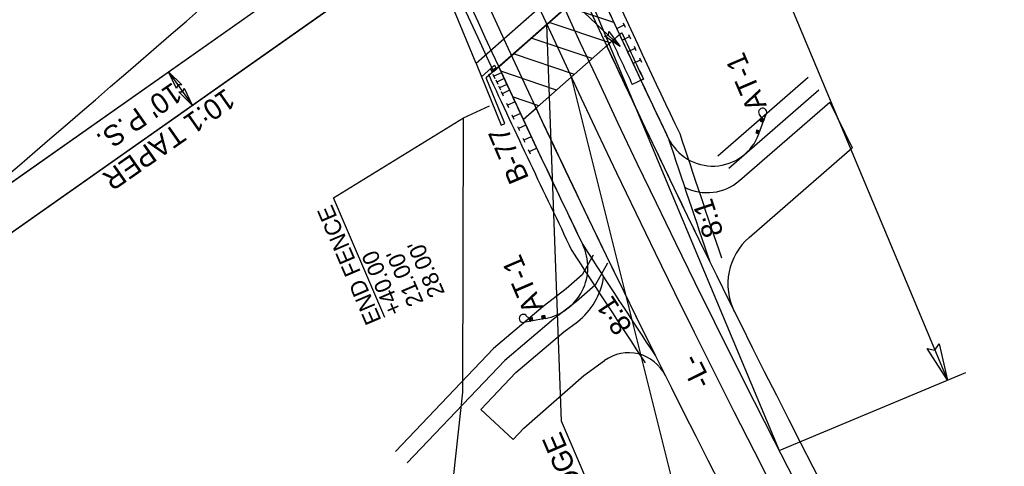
# Model space of a CAD drawing. Extents: x 1550950 to 1552827, y 809595 to 812050.
# Drawn here: x 1551746.5 to 1551986.2, y 810516.8 to 810625.6 of the extents above; entities that cross this region are included whole.
import ezdxf

# ---------------------------------------------------------------- set-up
doc = ezdxf.new("R2010")
doc.units = 0
for name, color, linetype in [('_CIVIL_CONSTRUCTION', 7, 'Continuous'), ('Construction Elements LEVEL', 7, 'Continuous'), ('Draft_Plan_Labels', 7, 'Continuous'), ('Drop Inlet Box Traffic Bearing 840 35-Bottom CELL', 7, 'Continuous'), ('Drop Inlet Box Type B 36 Dia-Bottom CELL', 7, 'Continuous'), ('Drop Inlet Grate 2 Narrow Slot and Flat Grates 840 29 36 Dia BD Apron-Top CELL', 7, 'Continuous'), ('Drop Inlet Grate 2 Narrow Slot and Flat Grates 840 29 36 Dia BD CELL', 7, 'Continuous'), ('Drop Inlet Grate 2 Narrow Slot and Flat Grates 840 29 36 Dia TB-Top CELL', 7, 'Continuous'), ('Drop Inlet Grate 2 Wide Slot and Flat Grates 840 20 36 Dia BD-Top CELL', 7, 'Continuous'), ('Drop Inlet Grate 3 Narrow Slot and Flat Grates 840 29 48 Dia-Top CELL', 7, 'Continuous'), ('E_NCDOT_Vertical_Profile_Ground_Line', 7, 'Continuous'), ('Junction Box with Slab Lid 840 31 66 Dia TB CELL', 7, 'Continuous'), ('P_HYD_Ditch_Flow_Arrow', 7, 'Continuous'), ('P_NCDOT_SS_Cut_Line', 7, 'Continuous'), ('P_NCDOT_SS_Transition_Line', 7, 'Continuous'), ('RipRap Pad at Outlet CELL', 7, 'Continuous'), ('Typical Terminator CELL', 7, 'Continuous'), ('V Ditch Special Lateral Detail CELL', 7, 'Continuous'), ('V Ditch Special Lateral with PSRM Detail CELL', 7, 'Continuous')]:
    doc.layers.add(name, color=color, linetype=linetype)

msp = doc.modelspace()

# ---------------------------------------------------------------- linework, layer by layer
at = {"layer": '_CIVIL_CONSTRUCTION'}
msp.add_line((1551782.78, 810612.91), (1551788.54, 810604.74), dxfattribs=at)
at = {"layer": 'Construction Elements LEVEL'}
for centre, radius, start, end in [((1554524.17, 811845.14), 2902, 205.10191, 205.4792), ((1551915.25, 810601.91), 12, 205.4792, 339.7079), ((1554524.17, 811845.14), 2932, 205.27393, 205.76247), ((1551872.17, 810565.26), 12.69, 280.4328, 25.7625)]:
    msp.add_arc(centre, radius, start, end, dxfattribs=at)
at = {"layer": 'Draft_Plan_Labels'}
for points in [[(1551871.67, 810641.73), (1551873.63, 810637.13), (1551892.72, 810619.04)], [(1551898.07, 810481.9), (1551878.45, 810527.75), (1551874.88, 810624.42)], [(1551941.7, 810409.34), (1551916.99, 810467.06), (1551880.83, 810611.6)], [(1551835.45, 810553.04), (1551822.97, 810582.2), (1551854.57, 810601.66)], [(1551862.89, 810445.08), (1551848.32, 810479.12), (1551854.4, 810534.8)]]:
    msp.add_lwpolyline(points, dxfattribs=at)
at = {"layer": 'Drop Inlet Box Traffic Bearing 840 35-Bottom CELL'}
for p, q in [((1551857.64, 810614.87), (1551844.4, 810647.29)), ((1551888.44, 810642.05), (1551857.64, 810614.87)), ((1551889.52, 810637.33), (1551860.13, 810611.4)), ((1551857.64, 810614.87), (1551863.75, 810599.91)), ((1551862.12, 810614.49), (1551858.94, 810611.68)), ((1551862.12, 810614.49), (1551862.56, 810613.54)), ((1551864.67, 810600.29), (1551860.13, 810611.4)), ((1551863.75, 810599.91), (1551864.67, 810600.29))]:
    msp.add_line(p, q, dxfattribs=at)
at = {"layer": 'Drop Inlet Box Type B 36 Dia-Bottom CELL'}
msp.add_line((1551738.42, 810569.43), (1551825.44, 810630.73), dxfattribs=at)
for centre, radius, start, end in [((1554524.17, 811845.14), 2902, 204.93866, 205.10191), ((1554524.17, 811845.14), 2902, 205.17218, 205.4792), ((1554524.17, 811845.14), 2932, 205.10292, 205.76247), ((1554653.7, 811503.31), 2894.89, 198.24966, 198.87905), ((1554332.71, 812152.3), 2915.37, 212.8525, 213.48904)]:
    msp.add_arc(centre, radius, start, end, dxfattribs=at)
at = {"layer": 'Drop Inlet Grate 2 Narrow Slot and Flat Grates 840 29 36 Dia BD Apron-Top CELL'}
for p, q in [((1551916.53, 810592.42), (1551938.49, 810611.53)), ((1551919.16, 810589.41), (1551941.12, 810608.51))]:
    msp.add_line(p, q, dxfattribs=at)
for points in [[(1551886.12, 810568.23), (1551883.43, 810563.41), (1551879.57, 810559.98), (1551874.01, 810555.72), (1551861.85, 810545.43), (1551838, 810520.39)], [(1551889.61, 810566.28), (1551886.59, 810560.88), (1551882.12, 810556.89), (1551876.52, 810552.61), (1551864.6, 810542.51), (1551840.9, 810517.63)]]:
    msp.add_lwpolyline(points, dxfattribs=at)
at = {"layer": 'Drop Inlet Grate 2 Narrow Slot and Flat Grates 840 29 36 Dia BD CELL'}
for p, q in [((1551800.94, 810947.98), (1551972.39, 810537.74)), ((1551759.95, 810930.85), (1551931.4, 810520.61)), ((1551931.4, 810520.61), (1551976.89, 810539.62))]:
    msp.add_line(p, q, dxfattribs=at)
msp.add_lwpolyline([(1551970.35, 810546.64), (1551972.39, 810537.74), (1551967.42, 810545.47), (1551969.34, 810545.03)], close=True, dxfattribs=at)
msp.add_arc((1554524.17, 811845.14), 2911.5, 194.24112, 221.47505, dxfattribs=at)
at = {"layer": 'Drop Inlet Grate 2 Narrow Slot and Flat Grates 840 29 36 Dia TB-Top CELL'}
for points in [[(1551889.99, 810622.69), (1551892.72, 810619.04), (1551888.88, 810621.57), (1551889.85, 810621.75)], [(1551784.74, 810608.79), (1551782.78, 810612.91), (1551786.04, 810609.67), (1551785.06, 810609.68)], [(1551786.58, 810608.86), (1551788.54, 810604.74), (1551785.28, 810607.98), (1551786.27, 810607.97)]]:
    msp.add_lwpolyline(points, close=True, dxfattribs=at)
at = {"layer": 'Drop Inlet Grate 2 Wide Slot and Flat Grates 840 20 36 Dia BD-Top CELL'}
msp.add_lwpolyline([(1551854.4, 810534.8), (1551854.57, 810601.66), (1551860.91, 810604.62)], dxfattribs=at)
at = {"layer": 'Drop Inlet Grate 3 Narrow Slot and Flat Grates 840 29 48 Dia-Top CELL'}
for p, q in [((1551889.43, 810619.19), (1551893.08, 810622.41)), ((1551898.37, 810611.09), (1551897.76, 810610.81)), ((1551869.11, 810601.25), (1551872.23, 810604.01))]:
    msp.add_line(p, q, dxfattribs=at)
msp.add_lwpolyline([(1551825.44, 810630.73), (1551738.42, 810569.43), (1551734.76, 810566.32), (1551727.95, 810574.29), (1551827.17, 810644.18)], dxfattribs=at)
for centre, radius, start, end in [((1554626.98, 811893.19), 3014.81, 204.93012, 205.16753), ((1554545.5, 811855.33), 2929.64, 204.95737, 206.09699), ((1554524.17, 811845.14), 2902, 205.17218, 205.4792), ((1554542.8, 811854.12), 2948.68, 205.08459, 206.38638), ((1554561.55, 811862.92), 2973.39, 205.10751, 205.75788), ((1554653.7, 811503.31), 2894.89, 198.24966, 198.87905), ((1554332.71, 812152.3), 2915.37, 212.8525, 213.48904)]:
    msp.add_arc(centre, radius, start, end, dxfattribs=at)
at = {"layer": 'E_NCDOT_Vertical_Profile_Ground_Line'}
for p, q in [((1551926.57, 810602.49), (1551927.22, 810601.48)), ((1551927.73, 810601.07), (1551928.33, 810602.69)), ((1551926.5, 810597.75), (1551927.73, 810601.07)), ((1551927.04, 810601.54), (1551926.8, 810600.88)), ((1551927.8, 810601.26), (1551926.8, 810600.88)), ((1551926.8, 810600.88), (1551927.56, 810600.6)), ((1551927.8, 810601.26), (1551927.04, 810601.54)), ((1551927.56, 810600.6), (1551927.04, 810601.54)), ((1551927.8, 810601.26), (1551927.47, 810601.38)), ((1551927.8, 810601.26), (1551927.47, 810601.38)), ((1551927.56, 810600.6), (1551927.8, 810601.26)), ((1551927.76, 810601.14), (1551927.71, 810601.01)), ((1551927.76, 810601.14), (1551927.71, 810601.01)), ((1551925.99, 810598.69), (1551925.75, 810598.03)), ((1551926.75, 810598.41), (1551925.75, 810598.03)), ((1551925.75, 810598.03), (1551926.5, 810597.75)), ((1551926.75, 810598.41), (1551925.99, 810598.69)), ((1551926.5, 810597.75), (1551925.99, 810598.69)), ((1551926.5, 810597.75), (1551926.75, 810598.41)), ((1551870.98, 810552.13), (1551869.3, 810551.82)), ((1551869.79, 810553.53), (1551870.6, 810552.78)), ((1551870.58, 810552.88), (1551871.27, 810553.01)), ((1551870.72, 810552.09), (1551870.58, 810552.88)), ((1551871.41, 810552.21), (1551870.58, 810552.88)), ((1551870.72, 810552.09), (1551870.66, 810552.43)), ((1551870.72, 810552.09), (1551870.66, 810552.43)), ((1551870.72, 810552.09), (1551871.27, 810553.01)), ((1551871.41, 810552.21), (1551870.72, 810552.09)), ((1551870.85, 810552.11), (1551870.98, 810552.13)), ((1551870.85, 810552.11), (1551870.98, 810552.13)), ((1551874.47, 810552.78), (1551870.98, 810552.13)), ((1551871.27, 810553.01), (1551871.41, 810552.21)), ((1551873.64, 810553.44), (1551874.32, 810553.57)), ((1551873.78, 810552.65), (1551873.64, 810553.44)), ((1551874.47, 810552.78), (1551873.64, 810553.44)), ((1551873.78, 810552.65), (1551874.32, 810553.57)), ((1551874.47, 810552.78), (1551873.78, 810552.65)), ((1551874.32, 810553.57), (1551874.47, 810552.78))]:
    msp.add_line(p, q, dxfattribs=at)
for centre, major_axis, start_param, end_param in [((1551927.4, 810603.03), (-0.931, 0.344), 3.141593, 7.214552), ((1551869.12, 810552.8), (0.18, -0.977), 2.210226, 6.283185)]:
    msp.add_ellipse(centre, major_axis=major_axis, ratio=0.995379, start_param=start_param, end_param=end_param, dxfattribs=at)
at = {"layer": 'Junction Box with Slab Lid 840 31 66 Dia TB CELL'}
for centre, radius, start, end in [((1554524.17, 811845.14), 2899, 204.64059, 205.48294), ((1554524.17, 811845.14), 2935, 204.83638, 205.7661), ((1554653.7, 811503.31), 2891.89, 198.2459, 198.87905), ((1554332.71, 812152.3), 2918.37, 212.84885, 213.48904)]:
    msp.add_arc(centre, radius, start, end, dxfattribs=at)
at = {"layer": 'P_HYD_Ditch_Flow_Arrow'}
msp.add_arc((1554524.17, 811845.14), 2917, 194.24112, 221.47505, dxfattribs=at)
at = {"layer": 'P_NCDOT_SS_Cut_Line'}
for p, q in [((1551891.21, 810624.85), (1551879.74, 810628.7)), ((1551890.24, 810619.9), (1551875.41, 810624.88)), ((1551885.91, 810616.08), (1551871.08, 810621.06)), ((1551881.58, 810612.26), (1551866.75, 810617.23)), ((1551877.25, 810608.44), (1551863.63, 810613)), ((1551872.92, 810604.62), (1551866.54, 810606.76))]:
    msp.add_line(p, q, dxfattribs=at)
at = {"layer": 'P_NCDOT_SS_Transition_Line'}
for p, q in [((1551886.63, 810634.78), (1551896.25, 810614.03)), ((1551891.89, 810623.44), (1551893.7, 810624.28)), ((1551893.46, 810624.8), (1551893.94, 810623.76)), ((1551893.2, 810620.61), (1551895.02, 810621.45)), ((1551894.78, 810621.97), (1551895.26, 810620.93)), ((1551896.09, 810619.13), (1551896.57, 810618.09)), ((1551894.52, 810617.77), (1551896.33, 810618.61)), ((1551863.15, 810614.06), (1551861.33, 810613.21)), ((1551863.15, 810614.06), (1551872.83, 810593.33)), ((1551895.83, 810614.94), (1551897.65, 810615.78)), ((1551897.4, 810616.3), (1551897.89, 810615.26)), ((1551861.09, 810613.73), (1551861.58, 810612.69)), ((1551861.75, 810612.31), (1551862.24, 810611.28)), ((1551863.81, 810612.64), (1551862, 810611.8)), ((1551862.41, 810610.9), (1551862.9, 810609.86)), ((1551864.47, 810611.23), (1551862.66, 810610.38)), ((1551863.08, 810609.48), (1551863.56, 810608.45)), ((1551865.13, 810609.81), (1551863.32, 810608.96)), ((1551863.74, 810608.07), (1551864.22, 810607.03)), ((1551865.79, 810608.4), (1551863.98, 810607.55)), ((1551865.06, 810605.24), (1551865.55, 810604.2)), ((1551867.12, 810605.57), (1551865.3, 810604.72)), ((1551866.38, 810602.41), (1551866.87, 810601.37)), ((1551868.44, 810602.73), (1551866.63, 810601.89)), ((1551867.71, 810599.58), (1551868.19, 810598.54)), ((1551869.76, 810599.9), (1551867.95, 810599.06)), ((1551869.03, 810596.74), (1551869.52, 810595.71)), ((1551871.09, 810597.07), (1551869.27, 810596.23)), ((1551870.35, 810593.91), (1551870.84, 810592.88)), ((1551872.41, 810594.24), (1551870.6, 810593.39))]:
    msp.add_line(p, q, dxfattribs=at)
at = {"layer": 'RipRap Pad at Outlet CELL'}
for p, q in [((1551890.73, 810620.34), (1551893.08, 810622.41)), ((1551898.37, 810611.09), (1551895.65, 810609.81))]:
    msp.add_line(p, q, dxfattribs=at)
for radius, start in [(2902, 204.92938), (2901.33, 204.92548), (2904.33, 204.94301)]:
    msp.add_arc((1554524.17, 811845.14), radius, start, 205.17218, dxfattribs=at)
at = {"layer": 'Typical Terminator CELL'}
msp.add_line((1551861.87, 810612.94), (1551887.9, 810635.9), dxfattribs=at)
for radius, start, end in [(2932, 199.81432, 204.82692), (2933.62, 199.82689, 204.83638)]:
    msp.add_arc((1554524.17, 811845.14), radius, start, end, dxfattribs=at)
at = {"layer": 'V Ditch Special Lateral Detail CELL'}
msp.add_line((1551892.56, 810621.95), (1551869.11, 810601.25), dxfattribs=at)
for radius, start, end in [(2902, 204.65027, 204.92938), (2932, 204.82692, 205.10292)]:
    msp.add_arc((1554524.17, 811845.14), radius, start, end, dxfattribs=at)
at = {"layer": 'V Ditch Special Lateral with PSRM Detail CELL'}
for p, q in [((1551727.95, 810574.29), (1551827.17, 810644.18)), ((1551921.78, 810586.39), (1551943.74, 810605.49)), ((1551943.74, 810605.49), (1551949.2, 810594.34)), ((1551924.09, 810572.49), (1551949.2, 810594.34)), ((1551858.78, 810530.6), (1551867.35, 810539.6)), ((1551858.78, 810530.6), (1551866.69, 810523.26))]:
    msp.add_line(p, q, dxfattribs=at)
for points in [[(1551867.35, 810539.6), (1551879.03, 810549.49), (1551882.31, 810552)], [(1551866.69, 810523.26), (1551869.25, 810526.05), (1551883.84, 810538.93), (1551888.93, 810542.56)]]:
    msp.add_lwpolyline(points, dxfattribs=at)
for centre, radius, start, end in [((1554524.17, 811845.14), 2906, 194.24112, 210.67194), ((1554524.17, 811845.14), 2928, 194.24112, 210.67194), ((1544245.73, 819324.67), 11459.16, 307.933611, 313.133611), ((1544245.73, 819324.67), 11513.16, 310.532877, 312.087357), ((1551913.91, 810595.44), 12, 242.6337, 311.0211), ((1551933.94, 810561.18), 15, 131.0211, 206.3674), ((1551872.17, 810565.26), 16.69, 307.4014, 351.9162), ((1551894.75, 810534.43), 10, 26.4952, 125.582)]:
    msp.add_arc(centre, radius, start, end, dxfattribs=at)

# ---------------------------------------------------------------- texts
at = {"layer": 'Draft_Plan_Labels'}
for s, height, rotation, p in [('AT-1', 5, 113.1736, (1551928.45, 810604.66)), ("10' P.S.", 5, 214.9526, (1551783.79, 810610.5)), ('10:1 TAPER', 5, 214.9526, (1551796.69, 810609.04)), ('B-77', 5, 113.1736, (1551870.6, 810586.96)), ('END FENCE', 4, 113.1736, (1551834.66, 810552.35)), ('8:1', 5, 108.6588, (1551917.95, 810573.54)), ("28.00'", 4, 113.1736, (1551850.1, 810558.96)), ('+40.00', 4, 113.1736, (1551839.81, 810554.56)), ("21.00'", 4, 113.1736, (1551844.95, 810556.76)), ('AT-1', 5, 113.2542, (1551874.06, 810555.43)), ('8:1', 5, 123.228, (1551895.82, 810550.91)), ('-L-', 5, 116.5591, (1551915.1, 810537.2)), ('BEGIN BRIDGE', 5, 113.1736, (1551897.18, 810481.08))]:
    msp.add_text(s, height=height, rotation=rotation, dxfattribs=at).set_placement(p)

doc.saveas('drawing.dxf')
